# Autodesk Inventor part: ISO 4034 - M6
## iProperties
Created: 2007-03
Part Number: ISO 4034 - M6
Material: Acier
Description: Ecrous hexagonaux - Produit de classe C
Document SubType Name: Modeling
Standard: ISO 4034
Designer: EF
Standard Revision: Troisième édition 1999-08-15
Standards Organization: ISO
Language: fr-FR
Size Designation: M6
Categories: <MemberInstance><Categories><Category DisplayName="Visserie" InternalName="e4da775c-781d-43d5-af7c-5136215cf5a6" Mnemonic="FSTN"><Category DisplayName="Ecrous"
Density: 1 g/cm^3
IsCustomPart: 0
Author: EF
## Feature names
1. Corps [Extrusion]
2. Chanfrein1 [Revolution]
3. Filetage [Hole]
4. Chanfrein2 [Chamfer]
5. Chanfrein3 [Chamfer]
